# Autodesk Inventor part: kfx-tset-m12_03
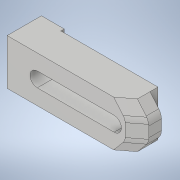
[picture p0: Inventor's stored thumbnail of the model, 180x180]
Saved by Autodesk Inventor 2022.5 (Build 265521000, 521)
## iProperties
Created: 2021-10
Part Number: kfx-tset-m12_03
Material: 一般
Document SubType Name: Modeling
Designer: ImaoCorp
Density: 1 g/cm^3
Appearance: 既定
Author: ImaoCorp
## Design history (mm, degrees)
feature "kfx-tset-m12_03"
node "ソリッド1"
